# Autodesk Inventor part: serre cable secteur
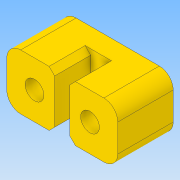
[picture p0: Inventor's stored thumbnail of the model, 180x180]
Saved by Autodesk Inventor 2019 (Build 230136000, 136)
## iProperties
Created: 2024-09
Part Number: serre cable secteur
Material: Générique
Document SubType Name: Modeling
Designer: admin
Density: 1 g/cm^3
Appearance: Par défaut
Author: admin
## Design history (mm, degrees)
sketch "Esquisse1"
  geometry: L1 (-8, 4)-(8, 4); L2 (8, 4)-(8, -4); L3 (8, -4)-(-8, -4); L4 (-8, -4)-(-8, 4); C1 r 1.35 at (-4, 0); C2 r 1.35 at (4, 0); 1 further point
  constraints: 8 end point, 2 centre point, 2 parallel, 1 horizontal, 1 perpendicular
  dimensions: "d0" = 8 distance of L1.end L2.end; "d1" = 4 distance from line of L1 point (0, 0) (= 0.5 x d0); "d2" = 16 distance of L1.start L1.end; "d3" = 8 distance from line of point (0, 0) L4 (= 0.5 x d2); "d4" = 2.7 diameter of C1; "d5" = 2.7 diameter of C2; "d6" = 4 distance of point (0, 0) C1.centre; "d7" = 4 distance of point (0, 0) C2.centre
extrude "Extrusion1" new body sketch "Esquisse1" distance "d8" = 8; taper "d9" = 0 deg
sketch "Esquisse2"
  geometry: L1 (8, 4)-(-8, 4) reference; L2 (-8, 4)-(-8, -4) reference; L3 (-8, -4)-(8, -4) reference; L4 (8, -4)-(8, 4) reference; L5 (-8, -4)-(8, -4) reference; L6 (-1.1, 4)-(1.1, 4); L7 (1.1, 4)-(1.1, -4); L8 (1.1, -4)-(-1.1, -4); L9 (-1.1, -4)-(-1.1, 4); C1 r 1.35 at (4, 0) reference; C2 r 1.35 at (-4, 0) reference; 1 further point
  constraints: 8 end point, 2 parallel, 2 point on line, 1 horizontal, 1 perpendicular
  dimensions: "d10" = 2.2 distance between parallel lines of L7 L9; "d11" = 1.1 distance from line of point (0, 0) L9 (= 0.5 x d10)
extrude "Extrusion2" cut sketch "Esquisse2" distance "d12" = 5.2; taper "d13" = 0 deg
fillet "Congé1" dims "d14" = 2
chamfer "Chanfrein1" distance "d15" = 0.8; stored, may be unused: second distance "d16" = 2, angle "d17" = 45 deg
node "Solide1"
node "Boucle projetée1"
